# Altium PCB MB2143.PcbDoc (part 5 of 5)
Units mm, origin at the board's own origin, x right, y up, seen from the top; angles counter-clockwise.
Board outline 70 x 70 mm, 4 copper layers (Top Layer, Signal Layer 1, Signal Layer 2, Bottom Layer), stack 1.56 mm thick; 272 components, 188 nets, 1083 pads, 1158 vias.
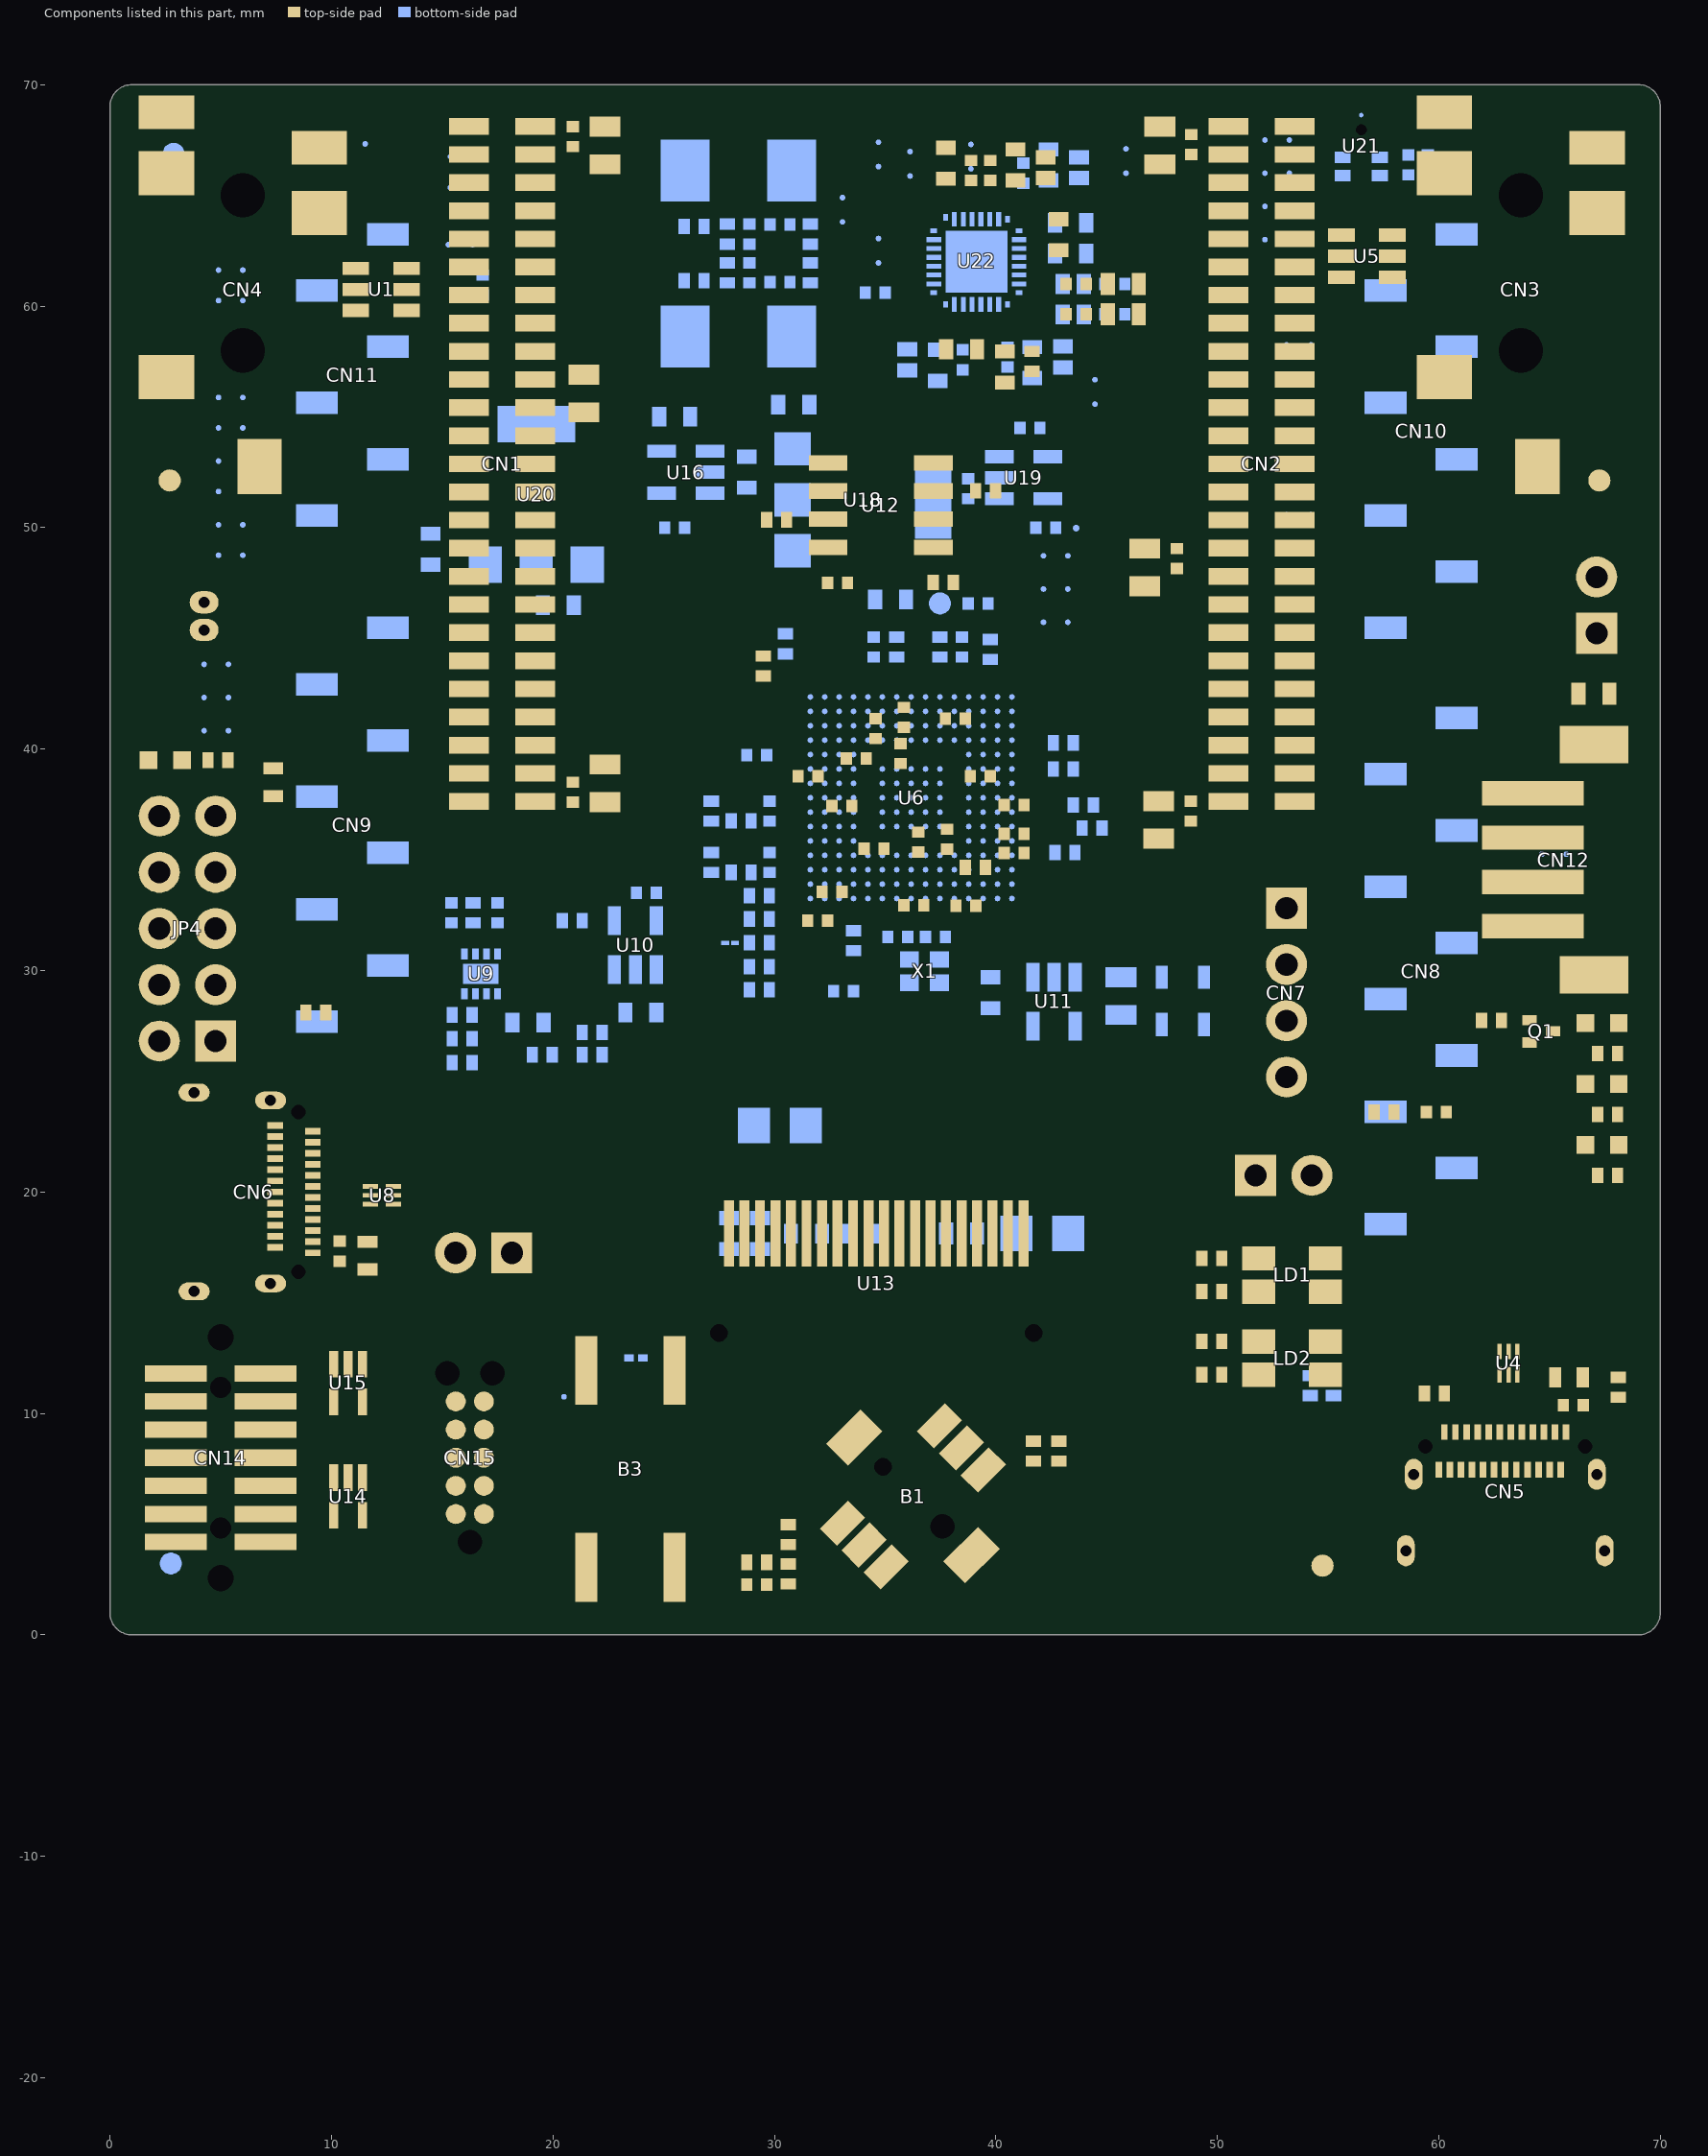
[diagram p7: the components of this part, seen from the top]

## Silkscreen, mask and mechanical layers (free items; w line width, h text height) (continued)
Drill Drawing:
  drawing of 291 lines, arcs and shapes, not listed
  text "THE COMPONENTS WITH PLATED THROUGH HOLE (PTH) MAY BE WELDED (CABLED) IN \"PIN-IN-PASTE\" MODE (IF NECESSARY)" at -62.125,120.625 h3
  text "PCB SPECIFICATIONS :" at -61.425,115.4 h3
  text "Layer" at 89.876,114.597 h2
  text "Name" at 98.245,114.597 h2
  text "Material" at 114.425,114.597 h2
  text "Thickness" at 129.789,114.597 h2
  text "Constant" at 141.733,114.597 h2
  text "MINIMUM PARAMETERS" at 158.15,113.867 h3
  text "A.   MATERIAL :" at -61.425,111.4 h3
  text "FR-4" at -22.925,111.4 h3
  text "TG-170" at -6.425,111.4 h3
  text "X  TG-150" at 11.825,111.4 h3
  text "TG-140" at 27.825,111.4 h3
  text "Top Overlay" at 98.245,110.597 h2
  text "B.   MATERIAL FAMILY :" at -61.425,108.4 h3
  text "N/A" at -22.925,108.4 h3
  text "DEFAULT" at 158.15,108.367 h3
  text "Top Solder" at 98.245,106.597 h2
  text "Solder Resist" at 114.425,106.597 h2
  text "0.020mm" at 129.789,106.597 h2
  text "3.5" at 141.733,106.597 h2
  text "C.   SOLDERMASK COLOR :" at -61.425,105.4 h3
  text "GREEN" at -22.925,105.4 h3
  text "X  BLUE" at -6.425,105.4 h3
  text "RED" at 11.825,105.4 h3
  text "BLACK" at 27.825,105.4 h3
  text "TRACKS : 0.12mm           / GAPS : 0.12mm" at 158.15,102.617 h3
  text "1" at 89.876,102.597 h2
  text "Top Layer" at 98.245,102.597 h2
  text "0.054mm" at 129.789,102.597 h2
  text "D.   SILKSCREEN COLOR :" at -61.425,102.4 h3
  text "X  WHITE" at -22.925,102.4 h3
  text "YELLOW" at -6.425,102.4 h3
  text "BLACK" at 11.825,102.4 h3
  text "E.   SURFACE FINISH :" at -61.425,99.4 h3
  text "X  ENIG" at -22.925,99.4 h3
  text "IMMERSION SILVER" at -6.425,99.4 h3
  text "IMMERSION TIN" at 27.825,99.4 h3
  text "Dielectric 1" at 98.245,98.597 h2
  text "1080HR RC68" at 114.425,98.597 h2
  text "0.076mm" at 129.789,98.597 h2
  text "4.2" at 141.733,98.597 h2
  text "HASL" at -22.925,96.4 h3
  text "HASL (PB-FREE)" at -6.425,96.4 h3
  text "GOLDEN FINGER" at 27.825,96.4 h3
  text "2" at 89.874,94.597 h2
  text "Signal Layer 1" at 98.245,94.597 h2
  text "0.035mm" at 129.789,94.597 h2
  text "PCB : TYPE 3" at 159.378,94.081 h3
  text "F.   IMPEDANCE CONTROL :" at -61.425,93.4 h3
  text "NO" at -22.925,93.4 h3
  text "X  YES  (SEE XLS FILE FOR DETAIL INFORMATION)" at -6.425,93.4 h3
  text "Dielectric 2" at 98.245,90.597 h2
  text "FR4" at 114.425,90.597 h2
  text "1.230mm" at 129.789,90.597 h2
  text "4.5" at 141.733,90.597 h2
  text "G.   THROUGH VIA :" at -61.425,90.4 h3
  text "PLUG THE VIAS WHICH ARE COVERED WITH SOLDERMASK ONE OR TWO SIDE." at -22.925,90.4 h3
  text "ASPECT-RATIO, AXE Z :" at 159.378,88.581 h3
  text "PLUG MATERIAL :" at -22.925,87.4 h3
  text "X  SOLDERMASK" at 2.575,87.4 h3
  text "NON-CONDUCTIVE EPOXY." at 27.825,87.4 h3
  text "3" at 89.876,86.597 h2
  text "Signal Layer 2" at 98.245,86.597 h2
  text "0.035mm" at 129.789,86.597 h2
  text "H.   STACK-UP :" at -61.425,84.4 h3
  text "SEE LAYER STACK-UP SEQUENCE FOR OVERALL THICKNESS." at -22.925,84.4 h3
  text "Dielectric 3" at 98.245,82.597 h2
  text "1080HR RC68" at 114.425,82.597 h2
  text "0.076mm" at 129.789,82.597 h2
  text "4.2" at 141.733,82.597 h2
  text "4" at 89.876,78.597 h2
  text "Bottom Layer" at 98.245,78.597 h2
  text "0.054mm" at 129.789,78.597 h2
  text "Bottom Solder" at 98.245,74.597 h2
  text "Solder Resist" at 114.425,74.597 h2
  text "0.020mm" at 129.789,74.597 h2
  text "3.5" at 141.733,74.597 h2
  text "DEFAULT / < 6:1 / LEVEL \"A\" /  / STLink / 6:1 A 8 : 1 / LEVEL \"B\"" at 159.25,70.625 h3
  text "Bottom Overlay" at 98.245,70.597 h2
  text "Symbol" at 86.739,61.773 h3
  text "Count" at 98.491,61.773 h3
  text "Via/Pad" at 111.764,61.773 h3
  text "Hole Size" at 124.072,61.773 h3
  text "Plated" at 138.345,61.773 h3
  text "Drill Layer Pair" at 148.662,61.773 h3
  text "Hole Type" at 177.104,61.773 h3
  text "Hole Length" at 192.124,61.773 h3
  text "Routed Path Length" at 209.312,61.773 h3
  text "1" at 98.491,56.595 h2.5
  text "Pad" at 111.764,56.595 h2.5
  text "0.500mm" at 124.072,56.595 h2.5
  text "NPTH" at 138.345,56.595 h2.5
  text "Top Layer - Bottom Layer" at 148.662,56.595 h2.5
  text "Round" at 177.104,56.595 h2.5
  text "-" at 192.124,56.595 h2.5
  text "-" at 209.312,56.595 h2.5
  text "2" at 98.491,51.416 h2.5
  text "Pad" at 111.764,51.416 h2.5
  text "0.500mm" at 124.072,51.416 h2.5
  text "PTH" at 138.345,51.416 h2.5
  text "Top Layer - Bottom Layer" at 148.662,51.416 h2.5
  text "Round" at 177.104,51.416 h2.5
  text "-" at 192.124,51.416 h2.5
  text "-" at 209.312,51.416 h2.5
  text "C" at 85.797,51.162 h2.3
  text "2" at 98.491,46.238 h2.5
  text "Pad" at 111.764,46.238 h2.5
  text "0.650mm" at 124.072,46.238 h2.5
  text "NPTH" at 138.345,46.238 h2.5
  text "Top Layer - Bottom Layer" at 148.662,46.238 h2.5
  text "Round" at 177.104,46.238 h2.5
  text "-" at 192.124,46.238 h2.5
  text "-" at 209.312,46.238 h2.5
  text "B" at 85.797,45.984 h2.3
  text "2" at 98.491,41.059 h2.5
  text "Pad" at 111.764,41.059 h2.5
  text "0.650mm" at 124.072,41.059 h2.5
  text "NPTH" at 138.345,41.059 h2.5
  text "Top Layer - Bottom Layer" at 148.662,41.059 h2.5
  text "Slot" at 177.104,41.059 h2.5
  text "0.950mm" at 192.124,41.059 h2.5
  text "0.300mm" at 209.312,41.059 h2.5
  text "2" at 98.491,35.881 h2.5
  text "Pad" at 111.764,35.881 h2.5
  text "0.970mm" at 124.072,35.881 h2.5
  text "NPTH" at 138.345,35.881 h2.5
  text "Top Layer - Bottom Layer" at 148.662,35.881 h2.5
  text "Round" at 177.104,35.881 h2.5
  text "-" at 192.124,35.881 h2.5
  text "-" at 209.312,35.881 h2.5
  text "2" at 98.491,30.702 h2.5
  text "Pad" at 111.764,30.702 h2.5
  text "1.190mm" at 124.072,30.702 h2.5
  text "NPTH" at 138.345,30.702 h2.5
  text "Top Layer - Bottom Layer" at 148.662,30.702 h2.5
  text "Round" at 177.104,30.702 h2.5
  text "-" at 192.124,30.702 h2.5
  text "-" at 209.312,30.702 h2.5
  text "3" at 98.491,25.524 h2.5
  text "Pad" at 111.764,25.524 h2.5
  text "0.800mm" at 124.072,25.524 h2.5
  text "NPTH" at 138.345,25.524 h2.5
  text "Top Layer - Bottom Layer" at 148.662,25.524 h2.5
  text "Round" at 177.104,25.524 h2.5
  text "-" at 192.124,25.524 h2.5
  text "-" at 209.312,25.524 h2.5
  text "4" at 98.491,20.346 h2.5
  text "Pad" at 111.764,20.346 h2.5
  text "1.100mm" at 124.072,20.346 h2.5
  text "NPTH" at 138.345,20.346 h2.5
  text "Top Layer - Bottom Layer" at 148.662,20.346 h2.5
  text "Round" at 177.104,20.346 h2.5
  text "-" at 192.124,20.346 h2.5
  text "-" at 209.312,20.346 h2.5
  text "4" at 98.491,15.167 h2.5
  text "Pad" at 111.764,15.167 h2.5
  text "2.000mm" at 124.072,15.167 h2.5
  text "NPTH" at 138.345,15.167 h2.5
  text "Top Layer - Bottom Layer" at 148.662,15.167 h2.5
  text "Round" at 177.104,15.167 h2.5
  text "-" at 192.124,15.167 h2.5
  text "-" at 209.312,15.167 h2.5
  text "8" at 98.491,9.989 h2.5
  text "Pad" at 111.764,9.989 h2.5
  text "0.500mm" at 124.072,9.989 h2.5
  text "PTH" at 138.345,9.989 h2.5
  text "Top Layer - Bottom Layer" at 148.662,9.989 h2.5
  text "Slot" at 177.104,9.989 h2.5
  text "1.100mm" at 192.124,9.989 h2.5
  text "0.600mm" at 209.312,9.989 h2.5
  text "20" at 98.491,4.81 h2.5
  text "Pad" at 111.764,4.81 h2.5
  text "1.000mm" at 124.072,4.81 h2.5
  text "PTH" at 138.345,4.81 h2.5
  text "Top Layer - Bottom Layer" at 148.662,4.81 h2.5
  text "Round" at 177.104,4.81 h2.5
  text "-" at 192.124,4.81 h2.5
  text "-" at 209.312,4.81 h2.5
  text "50" at 98.491,-0.368 h2.5
  text "Via" at 111.764,-0.368 h2.5
  text "0.200mm" at 124.072,-0.368 h2.5
  text "PTH" at 138.345,-0.368 h2.5
  text "Top Layer - Bottom Layer" at 148.662,-0.368 h2.5
  text "Round" at 177.104,-0.368 h2.5
  text "-" at 192.124,-0.368 h2.5
  text "-" at 209.312,-0.368 h2.5
  text "A" at 85.797,-0.622 h2.3
  text "1108" at 98.491,-5.547 h2.5
  text "Via" at 111.764,-5.547 h2.5
  text "0.300mm" at 124.072,-5.547 h2.5
  text "PTH" at 138.345,-5.547 h2.5
  text "Top Layer - Bottom Layer" at 148.662,-5.547 h2.5
  text "Round" at 177.104,-5.547 h2.5
  text "-" at 192.124,-5.547 h2.5
  text "-" at 209.312,-5.547 h2.5
  text "1208 Total" at 98.491,-10.725 h2.5
  text "Slot definitions :" at 86.739,-14.35 h2.5
  text "Routed Path Length" at 103.779,-14.35 h2.5
  text "= Calculated from tool start centre position to tool end centre position." at 124.898,-14.35 h2.5
  text "Hole Length" at 103.779,-16.421 h2.5
  text "= Routed Path Length + Tool Size = Slot length as defined in the PCB layout" at 117.058,-16.421 h2.5

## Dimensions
70,70 to 70,0 on M2-Board Dimensions
0,70 to 70,70 on M2-Board Dimensions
